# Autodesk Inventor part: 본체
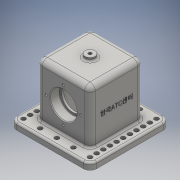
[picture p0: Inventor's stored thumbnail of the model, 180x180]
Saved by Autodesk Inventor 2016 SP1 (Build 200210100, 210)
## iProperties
Created: 2018-11
Part Number: 본체
Material: 일반
Document SubType Name: Modeling
Designer: basic
Density: 1 g/cm^3
Appearance: 기본값
Author: basic
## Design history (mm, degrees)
sketch "스케치1"
  geometry: L1 (-60, -60)-(60, -60); L2 (60, -60)-(60, 60); L3 (60, 60)-(-60, 60); L4 (-60, 60)-(-60, -60); L5 (-60, -60)-(60, 60); L6 (60, -60)-(-60, 60); 1 further point
  constraints: 12 end point, 2 midpoint, 2 parallel, 2 perpendicular, 1 horizontal
  dimensions: "d0" = 120 distance of L2.end L3.end
extrude "돌출1" new body sketch "스케치1" distance "d1" = 10; taper "d2" = 0 deg
sketch "스케치2"
  geometry: L1 (-40, -40)-(40, -40); L2 (40, -40)-(40, 40); L3 (40, 40)-(-40, 40); L4 (-40, 40)-(-40, -40); L5 (-40, -40)-(40, 40); L6 (40, -40)-(-40, 40); 1 further point
  constraints: 12 end point, 2 midpoint, 2 parallel, 2 perpendicular, 1 horizontal
  dimensions: "d3" = 80 distance of L2.end L3.end
extrude "돌출2" join sketch "스케치2" distance "d4" = 80; taper "d5" = 0 deg
sketch "스케치3"
  geometry: L1 (40, -10)-(40, 38); C1 r 20 at (40, 38)
  constraints: 2 end point, 1 centre point, 1 coincident, 1 vertical
  dimensions: "d6" = 48 distance of L1.start L1.end; "d7" = 40 diameter of C1
extrude "돌출3" cut sketch "스케치3" distance "d8" = 14; taper "d9" = 0 deg
sketch "스케치4"
  geometry: C1 r 20 at (0, 0) reference; C2 r 16.5 at (0, 0); 1 further point
  constraints: 1 centre point, 1 coincident
  dimensions: "d11" = 33 diameter of C2
extrude "돌출4" cut sketch "스케치4" distance "d12" = 3; taper "d13" = 0 deg
sketch "스케치5"
  geometry: L1 (30, -23)-(-30, -23); L2 (-30, -23)-(-30, 23); L3 (-30, 23)-(30, 23); L4 (30, 23)-(30, -23); L5 (30, -23)-(-30, 23); L6 (-30, -23)-(30, 23); 1 further point
  constraints: 12 end point, 2 midpoint, 2 parallel, 1 horizontal, 1 perpendicular
  dimensions: "d14" = 60 distance of L2.end L3.end; "d15" = 46 distance of L1.end L2.end
extrude "돌출5" cut sketch "스케치5" distance "d16" = 80; taper "d17" = 0 deg
sketch "스케치6"
  geometry: L1 (40, 38)-(40, 64); C1 r 20 at (40, 38) reference; 2 further points
  constraints: 2 end point, 1 coincident, 1 vertical
  dimensions: "d19" = 26 distance of L1.start L1.end
hole "구멍1" sketch "스케치6" at (40, 64) diameter "d20" = 3.242; stored, may be unused: countersink angle "d24" = 90 deg, drill point angle "d26" = 118 deg; dims "d21" = 8, "d22" = 4, "d23" = 2, "d25" = 10
node "작업 평면1"
sketch "스케치7"
  geometry: C1 r 7.5 at (0, 0); 1 further point
  constraints: 1 centre point, 1 coincident
  dimensions: "d31" = 15 diameter of C1
extrude "돌출6" join sketch "스케치7" stored distance "d32" = 80; taper "d33" = 0 deg
sketch "스케치8"
  geometry: 2 further points
  constraints: 1 coincident
hole "구멍2" sketch "스케치8" at (0, 0) diameter "d34" = 4.917; stored, may be unused: countersink angle "d38" = 90 deg, drill point angle "d40" = 118 deg; dims "d35" = 12, "d36" = 4, "d37" = 2, "d39" = 17.1
fillet "모깎기1" dims "d41" = 10
sketch "스케치9"
  geometry: A1 r 10 centre (-50, -50) between (-60, -50) and (-50, -60) reference; 2 further points
  constraints: 1 coincident
hole "구멍3" sketch "스케치9" at (-50, -50) diameter "d42" = 6.6; stored, may be unused: countersink angle "d46" = 90 deg, drill point angle "d48" = 118 deg; dims "d43" = 12, "d44" = 4, "d45" = 2, "d47" = 17.1
fillet "모깎기2" dims "d68" = 8
fillet "모깎기3" dims "d69" = 8
fillet "모깎기4" dims "d70" = 3
fillet "모깎기5" dims "d71" = 3
fillet "모깎기6" dims "d72" = 3
fillet "모깎기7" dims "d73" = 0.6
chamfer "모따기1" distance "d74" = 1; stored, may be unused: second distance "d75" = 2, angle "d76" = 45 deg
fillet "모깎기8" dims "d77" = 3
fillet "모깎기9" dims "d78" = 3
sketch "스케치11"
  geometry: L1 (82, -18)-(82, 82) reference; 3 further points
  constraints: 1 horizontal alignment, 1 midpoint, 1 other
  dimensions: "d79" = 48 distance from line of L1 point (34, 32)
feature "엠보싱1" sketch "스케치11" dims "d0" = 120, "d80" = 0.5, "d81" = 0
node "솔리드1"
pattern_circular "원형 패턴1" dims angle "d28" = 360 deg
mirror "대칭1"
pattern_linear "직사각형 패턴1" dims "d51" = 25
pattern_linear "직사각형 패턴2"
mirror "대칭2"
mirror "대칭3"
other parameters: "d30" = 95
